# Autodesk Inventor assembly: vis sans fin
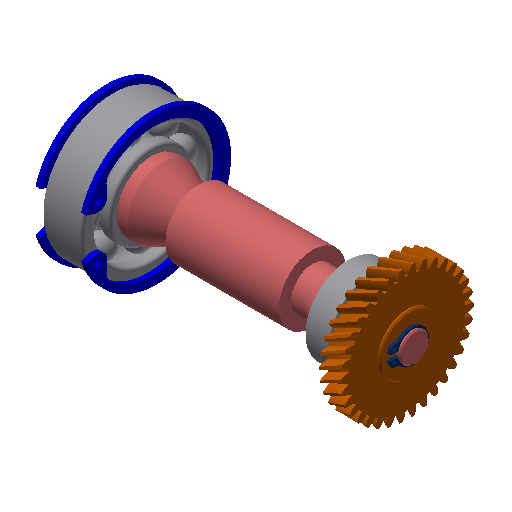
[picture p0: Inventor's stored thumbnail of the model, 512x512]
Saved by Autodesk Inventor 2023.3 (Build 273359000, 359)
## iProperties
Created: 2012-12
Part Number: vis sans fin
Document SubType Name: Assembly
Designer: jost thierry
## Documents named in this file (10)
- E:\Dossier technique\Reducteur\TD02-Reducteur S37\TD02-Reducteur-Ressources\TD02-Reduct-3D\vis sans fin.iam
- E:\Dossier technique\Reducteur\TD02-Reducteur S37\TD02-Reducteur-Ressources\TD02-Reduct-3D\VIS SANS FIN.ipt
- E:\Dossier technique\Reducteur\TD02-Reducteur S37\TD02-Reducteur-Ressources\TD02-Reduct-3D\roulement 15 32 9.iam
- E:\Dossier technique\Reducteur\TD02-Reducteur S37\TD02-Reducteur-Ressources\TD02-Reduct-3D\roulement 20 52 15.iam
- E:\Dossier technique\Reducteur\TD02-Reducteur S37\TD02-Reducteur-Ressources\TD02-Reduct-3D\ROUE 2.ipt
- E:\Dossier technique\Reducteur\TD02-Reducteur S37\TD02-Reducteur-Ressources\TD02-Reduct-3D\CLAVETTE C.ipt
- E:\Dossier technique\Reducteur\TD02-Reducteur S37\TD02-Reducteur-Ressources\TD02-Reduct-3D\anneauint55.ipt
- E:\Dossier technique\Reducteur\TD02-Reducteur S37\TD02-Reducteur-Ressources\TD02-Reduct-3D\Rondelle d'épaulement.ipt
- E:\Dossier technique\Reducteur\TD02-Reducteur S37\TD02-Reducteur-Ressources\TD02-Reduct-3D\anneau-élast-ext-10.ipt
- E:\Dossier technique\Reducteur\TD02-Reducteur S37\TD02-Reducteur-Ressources\TD02-Reduct-3D\anneau-élast-ext 20.ipt
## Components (10 placed, 9 different names)
1. VIS SANS FIN:1
2. roulement 15 32 9:1 [sub-assembly]
3. roulement 20 52 15:1 [sub-assembly]
4. ROUE 2:1
5. CLAVETTE C:1
6. anneauint55:1
7. anneauint55:2
8. Rondelle d'épaulement:1
9. anneau-élast-ext-10:1
10. anneau-élast-ext 20:1
